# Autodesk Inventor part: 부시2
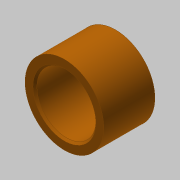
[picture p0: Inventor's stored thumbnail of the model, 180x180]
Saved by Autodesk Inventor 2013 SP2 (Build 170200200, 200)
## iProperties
Created: 2016-08
Part Number: 부시2
Material: 강철, 탄소
Document SubType Name: Modeling
Designer: mduedu
Density: 7.87 g/cm^3
Author: mduedu
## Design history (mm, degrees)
sketch "스케치1"
  geometry: C1 r 7.5 at (0, 0); C2 r 10 at (0, 0); 1 further point
  constraints: 2 centre point, 2 coincident
  dimensions: "d0" = 15 diameter of C1; "d1" = 20 diameter of C2
extrude "돌출1" new body sketch "스케치1" stored distance "d2" = 13; taper "d3" = 0 deg
chamfer "모따기1" distance "d4" = 0.5; stored, may be unused: second distance "d5" = 2, angle "d6" = 45 deg
node "솔리드1"
